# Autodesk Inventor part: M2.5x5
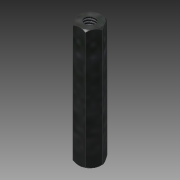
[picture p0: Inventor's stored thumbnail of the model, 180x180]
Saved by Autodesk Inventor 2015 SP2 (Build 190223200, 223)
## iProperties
Created: 2012-08
Part Number: M2.5x5
Material: Stahl
Document SubType Name: Modeling
Designer: rYan
Mass: 3.36246 g
Surface Area: 5.74911 cm^2
Volume: 0.428339 cm^3
Density: 7.85 g/cm^3
Appearance: Platte
Author: rYan
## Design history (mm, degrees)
derived "Abstandsbolzen Typ A.ipt"
feature "Volumenkörper1::Abstandsbolzen Typ A.ipt"
tag "Bezeichnung1"
node "Volumenkörper1"
other parameters: "SW" = 4, "L" = 22, "d2" = 0, "d16" = 45 deg
